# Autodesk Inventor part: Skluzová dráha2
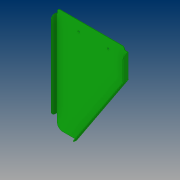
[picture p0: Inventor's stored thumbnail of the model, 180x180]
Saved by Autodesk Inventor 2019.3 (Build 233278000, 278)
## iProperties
Created: 2019-03
Part Number: Skluzová dráha2
Material: Ocel, legovaná
Document SubType Name: Plech
Designer: B-hon
Density: 7.73 g/cm^3
Sheet Metal Rule: Výchozí_mm
Appearance: Tmavě zelená
Author: B-hon
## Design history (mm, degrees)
node "Plocha1"
  sketch "Náčrt1"
    geometry: L1 (0, 0)-(330, 0); L2 (330, 0)-(330, -120); L3 (0, -475)-(0, 0); L4 (0, -475)-(96, -475); L5 (96, -475)-(330, -120)
    constraints: 10 end point, 2 horizontal, 1 parallel, 1 perpendicular
    dimensions: "d2" = 475 distance of L3.start L1.start; "d3" = 96 distance of L3.start L4.end; "d4" = 120 distance of L1.end L2.end; "d59" = 330 distance of L1.start L1.end
sketch "Náčrt2"
  geometry: L1 (334.786, 7.261)-(311, 7.261); L2 (311, 7.261)-(311, -13); L3 (311, -13)-(334.786, -13); L4 (334.786, -13)-(334.786, 7.261); L5 (0, -475)-(0, 0) reference; L6 (0, 0)-(330, 0) reference
  constraints: 8 end point, 2 parallel, 1 horizontal, 1 perpendicular
  dimensions: "d6" = 311 distance between parallel lines of L2 L5; "d7" = 13 distance between parallel lines of L3 L6
extrude "Vysunutí1" cut sketch "Náčrt2" distance "d8" = 10; taper "d9" = 0 deg
node "Obruba1"
sketch "Náčrt4"
  geometry: L1 (-22.159, 9.34)-(6, 9.34); L2 (6, 9.34)-(6, -20); L3 (6, -20)-(-22.159, -20); L4 (-22.159, -20)-(-22.159, 9.34); L5 (0, 0)-(311, 0) reference
  constraints: 8 end point, 2 parallel, 1 horizontal, 1 perpendicular
  dimensions: "d21" = 6 distance from line of L5.start L2; "d22" = 20 distance between parallel lines of L5 L3
extrude "Vysunutí2" cut sketch "Náčrt4" distance "d23" = 10; taper "d24" = 0 deg
fillet "Zaoblení2" dims "d25" = 10
node "Obruba2"
sketch "Náčrt6"
  geometry: L1 (95, -22)-(245, -22); L2 (245, -22)-(245, -67); L3 (245, -67)-(95, -67); L4 (95, -67)-(95, -22); L5 (16, 0)-(311, 0) reference; L6 (0, -20)-(0, -475) reference; 3 further points
  constraints: 8 end point, 2 parallel, 1 horizontal, 1 horizontal alignment, 1 perpendicular
  dimensions: "d36" = 22 distance between parallel lines of L1 L5; "d37" = 45 distance of L1.end L2.end; "d38" = 150 distance of L2.end L3.end; "d39" = 95 distance between parallel lines of L6 L4; "d40" = 8 distance from line of point (103, -44.5) L4; "d41" = 8 distance from line of L2 point (237, -44.5); "d42" = 22.5 distance from line of L1 point (103, -44.5)
hole "Díra1" sketch "Náčrt6" at (103, -44.5), (237, -44.5) diameter "d43" = 4.3; stored, may be unused: countersink angle "d47" = 90 deg, drill point angle "d49" = 118 deg; dims "d44" = 6, "d45" = 8.7, "d46" = 2, "d48" = 2 (= Tloušťka)
sketch "Náčrt7"
  geometry: L1 (-5.39, 60)-(5, 60); L2 (5, 60)-(5, -9.708); L3 (5, -9.708)-(-5.39, -9.708); L4 (-5.39, -9.708)-(-5.39, 60); L5 (4, 455)-(4, 0) reference; L6 (91.209, 0)-(4, 0) reference; 1 further point
  constraints: 8 end point, 2 parallel, 1 horizontal, 1 perpendicular
  dimensions: "d50" = 1 distance between parallel lines of L2 L5; "d51" = 60 distance between parallel lines of L6 L1
extrude "Vysunutí3" cut sketch "Náčrt7" distance "d52" = 50; taper "d53" = 0 deg
fillet "Zaoblení3" dims "d54" = 15
fillet "Zaoblení4" dims "d55" = 25
fillet "Zaoblení5" dims "d56" = 15
fillet "Zaoblení6" dims "d57" = 15
fillet "Zaoblení7" dims "d58" = 10
chamfer "Zkosení2" distance "d63" = 3; stored, may be unused: second distance "d64" = 2, angle "d65" = 60 deg
node "Těleso1"
feature "Deska1" dims "d5" = 2 (= Tloušťka)
sketch "Náčrt3"
  geometry: L1 through (-53.5, 0) direction (1, 0); L2 through (0, 12.5) direction (0, 1); L3 (0, 25)-(-107, 25); L4 (-107, 25)-(-107, 0)
  constraints: 6 end point, 1 horizontal, 1 perpendicular, 1 vertical
feature "Deska2" dims "d5" = 2 (= Tloušťka), "d11" = 2 (= ŠířkaVýštipu), "d12" = 1 (= HloubkaVýštipu), "d13" = 4 (= MinimálníZbytek), "d14" = 2 (= PřechodovýPoloměr), "d15" = 25, "d16" = 90 deg, "d17" = 2 (= PoloměrOhybu), "d18" = 8 (= VelikostRohovéhoVýštipu), "d19" = 2 (= VelikostMezery), "d20" = 2 (= VelikostJacobihoPoloměru), "MezeraVystřižení" = 0.01
feature "Ohyb1" dims "d5" = 2 (= Tloušťka), "d11" = 2 (= ŠířkaVýštipu), "d12" = 1 (= HloubkaVýštipu), "d13" = 4 (= MinimálníZbytek), "d14" = 2 (= PřechodovýPoloměr), "d15" = 25, "d16" = 90 deg, "d17" = 2 (= PoloměrOhybu), "MezeraVystřižení" = 0.01
feature "Roh1" dims "d15" = 25, "d16" = 90 deg, "d18" = 8 (= VelikostRohovéhoVýštipu), "d19" = 2 (= VelikostMezery), "d20" = 2 (= VelikostJacobihoPoloměru)
sketch "Náčrt5"
  geometry: L1 through (-227.5, 0) direction (1, 5.1e-36); L2 through (0, 12.5) direction (-1.22e-32, 1); L3 (0, 25)-(-455, 25); L4 (-455, 25)-(-455, 0)
  constraints: 6 end point, 1 horizontal, 1 perpendicular, 1 vertical
feature "Deska3" dims "d5" = 2 (= Tloušťka), "d26" = 2 (= ŠířkaVýštipu), "d27" = 1 (= HloubkaVýštipu), "d28" = 4 (= MinimálníZbytek), "d29" = 2 (= PřechodovýPoloměr), "d30" = 25, "d31" = 90 deg, "d32" = 2 (= PoloměrOhybu), "d33" = 8 (= VelikostRohovéhoVýštipu), "d34" = 2 (= VelikostMezery), "d35" = 2 (= VelikostJacobihoPoloměru), "MezeraVystřižení" = 0.01
feature "Ohyb2" dims "d5" = 2 (= Tloušťka), "d26" = 2 (= ŠířkaVýštipu), "d27" = 1 (= HloubkaVýštipu), "d28" = 4 (= MinimálníZbytek), "d29" = 2 (= PřechodovýPoloměr), "d30" = 25, "d31" = 90 deg, "d32" = 2 (= PoloměrOhybu), "MezeraVystřižení" = 0.01
feature "Roh2" dims "d30" = 25, "d31" = 90 deg, "d33" = 8 (= VelikostRohovéhoVýštipu), "d34" = 2 (= VelikostMezery), "d35" = 2 (= VelikostJacobihoPoloměru)
other parameters: "Tloušťka" = 2 (derived), "KSoučinitel" = 4.4, "PoloměrOhybu" = 2 (= Tloušťka), "ŠířkaVýštipu" = 2 (= Tloušťka), "HloubkaVýštipu" = 1 (= 0.5 x Tloušťka), "VelikostRohovéhoVýštipu" = 8 (= 4 x Tloušťka), "MinimálníZbytek" = 4 (= 2 x Tloušťka), "PřechodovýPoloměr" = 2 (= PoloměrOhybu), "VelikostJacobihoPoloměru" = 2 (= PoloměrOhybu), "VelikostMezery" = 2 (= Tloušťka)
